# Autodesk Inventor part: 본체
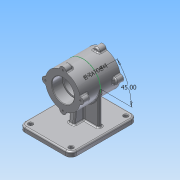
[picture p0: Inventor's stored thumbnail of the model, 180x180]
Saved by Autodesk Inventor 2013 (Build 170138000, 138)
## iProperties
Created: 2015-12
Part Number: 본체
Material: 알루미늄 6061
Document SubType Name: Modeling
Designer: user-11
Density: 2.71 g/cm^3
Mass: 1174.47 g
Surface Area: 817.122 cm^2
Volume: 433.385 cm^3
Author: user-11
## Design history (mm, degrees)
sketch "스케치1"
  geometry: C1 r 37 at (0, 0); 1 further point
  constraints: 1 centre point, 1 coincident
  dimensions: "d0" = 74 diameter of C1
extrude "돌출1" new body sketch "스케치1" stored distance "d2" = 85; taper "d3" = 0 deg
sketch "스케치2"
  geometry: C1 r 7 at (0, 37); 1 further point
  constraints: 2 vertical alignment, 1 centre point, 1 other
  dimensions: "d4" = 14 diameter of C1
extrude "돌출2" join sketch "스케치2" distance "d7" = 15; taper "d8" = 0 deg
node "작업 평면1"
node "작업 평면2"
sketch "스케치4"
  geometry: L1 (55, 80)-(-55, 80); L2 (-55, 80)-(-55, -60); L3 (-55, -60)-(55, -60); L4 (55, -60)-(55, 80); 2 further points
  constraints: 8 end point, 2 parallel, 1 horizontal, 1 midpoint, 1 perpendicular, 1 vertical alignment
  dimensions: "d14" = 55 distance from line of L4 point (0, 0); "d15" = 80 distance from line of L1 point (0, 0); "d16" = 140 distance of L3.end L1.start
extrude "돌출4" join sketch "스케치4" distance "d17" = 10; taper "d18" = 0 deg
sketch "스케치5"
  geometry: L1 (-55, -80)-(55, -80) reference; L2 (-55, 60)-(-55, -80) reference; C1 r 4 at (-43, -68); 1 further point
  constraints: 1 centre point
  dimensions: "d19" = 12 distance from line of L1 C1.centre; "d20" = 12 distance from line of C1.centre L2; "d21" = 8 diameter of C1
extrude "돌출5" cut sketch "스케치5" distance "d22" = 10; taper "d23" = 0 deg
sketch "스케치7"
  geometry: L1 (-55, -80)-(55, -80) reference; L2 (55, 60)-(-55, 60) reference; L3 (-6, 4)-(6, 4); L4 (6, 4)-(6, -4); L5 (6, -4)-(-6, -4); L6 (-6, -4)-(-6, 4); 3 further points
  constraints: 8 end point, 2 midpoint, 2 parallel, 1 horizontal, 1 perpendicular, 1 vertical alignment
  dimensions: "d30" = 8 distance of L5.end L3.start; "d32" = 12 distance of L3.start L3.end; "d33" = 84 distance between parallel lines of L1 L3
extrude "돌출6" join sketch "스케치7" stored distance "d34" = 10; taper "d35" = 0 deg
sketch "스케치8"
  geometry: L1 (-70, -60)-(-70, 80) reference; L2 (-37, -42.5)-(-37, 42.5) reference; L3 (-70, -25)-(-37, -20.948); L4 (-36.51, -4)-(-36.51, 4) reference; L5 (-70, -4)-(-36.51, -4) reference; L6 (-70, 4)-(-70, -4) reference; L7 (-70, 4)-(-36.51, 4) reference; 1 further point
  constraints: 2 end point, 2 point on line
  dimensions: "d36" = 29 distance of L3.start L6.start; "d37" = 97 deg angle of L3 L1
feature "리브1" sketch "스케치8" dims "d38" = 1, "d39" = 12, "d40" = 0, "d41" = 0, "d42" = 1, "d43" = 1
node "작업 평면3"
sketch "스케치9"
  geometry: L1 (-6, -70)-(6, -70) reference; L2 (55, -70)-(-55, -70) reference; L3 (-37, -70)-(-37, 0); 2 further points
  constraints: 2 end point, 1 horizontal alignment, 1 point on line, 1 vertical, 1 other
  dimensions: "d45" = 37 distance from line of L3 point (0, 0)
feature "리브2" sketch "스케치9" dims "d46" = 1, "d47" = 8, "d48" = 0, "d49" = 0, "d50" = 1, "d51" = 1
sketch "스케치10"
  geometry: C1 r 23.5 at (0, 0); A1 r 37 centre (0, 0) between (-6.969, 36.338) and (6.969, 36.338) reference
  constraints: 1 centre point, 1 coincident
  dimensions: "d52" = 47 diameter of C1
extrude "돌출7" cut sketch "스케치10" distance "d54" = 22; taper "d55" = 0 deg
sketch "스케치11"
  geometry: C1 r 23.5 at (0, 0) reference; C2 r 20.5 at (0, 0)
  constraints: 1 centre point, 1 coincident
  dimensions: "d56" = 41 diameter of C2
extrude "돌출8" cut sketch "스케치11" distance "d58" = 41; taper "d59" = 0 deg
sketch "스케치12"
  geometry: L1 (37, 0)-(0, 0); L2 (0, 0)-(26.163, 26.163); A1 r 37 centre (0, 0) between (37, 0) and (26.163, 26.163) reference; 1 further point
  constraints: 4 end point, 2 point on circle, 1 horizontal
  dimensions: "d60" = 45 deg angle of L2 L1
node "작업 평면4"
sketch "스케치13"
  geometry: 2 further points
  constraints: 1 coincident, 1 other
feature "엠보싱1" sketch "스케치13" dims "d0" = 74, "d61" = 0.5, "d62" = 0
fillet "모깎기1" dims "d63" = 3
fillet "모깎기2" dims "d64" = 3
fillet "모깎기3" dims "d65" = 12
fillet "모깎기4" dims "d66" = 3
fillet "모깎기5" dims "d67" = 3
fillet "모깎기6" dims "d68" = 3
fillet "모깎기7" dims "d69" = 3
fillet "모깎기8" dims "d70" = 0.3
chamfer "모따기1" distance "d71" = 1; stored, may be unused: second distance "d72" = 2, angle "d73" = 45 deg
sketch "스케치14"
  geometry: A1 r 7 centre (0, 37) between (6.889, 38.239) and (-6.889, 38.239) reference; 1 further point
  constraints: 1 coincident
hole "구멍1" sketch "스케치14" at (0, 37) diameter "d74" = 3.242; stored, may be unused: countersink angle "d78" = 90 deg, drill point angle "d80" = 118 deg; dims "d75" = 9, "d76" = 4, "d77" = 2, "d79" = 11
chamfer "모따기2" distance "d84" = 1; stored, may be unused: second distance "d85" = 2, angle "d86" = 45 deg
node "솔리드1"
pattern_linear "직사각형 패턴1" dims "d26" = 86, "d29" = 116
mirror "대칭1"
mirror "대칭2"
mirror "대칭3"
pattern_circular "원형 패턴1" dims "d82" = 360 deg
mirror "대칭4"
node "투영된 루프1"
other parameters: "d9" = 0, "d44" = 0
